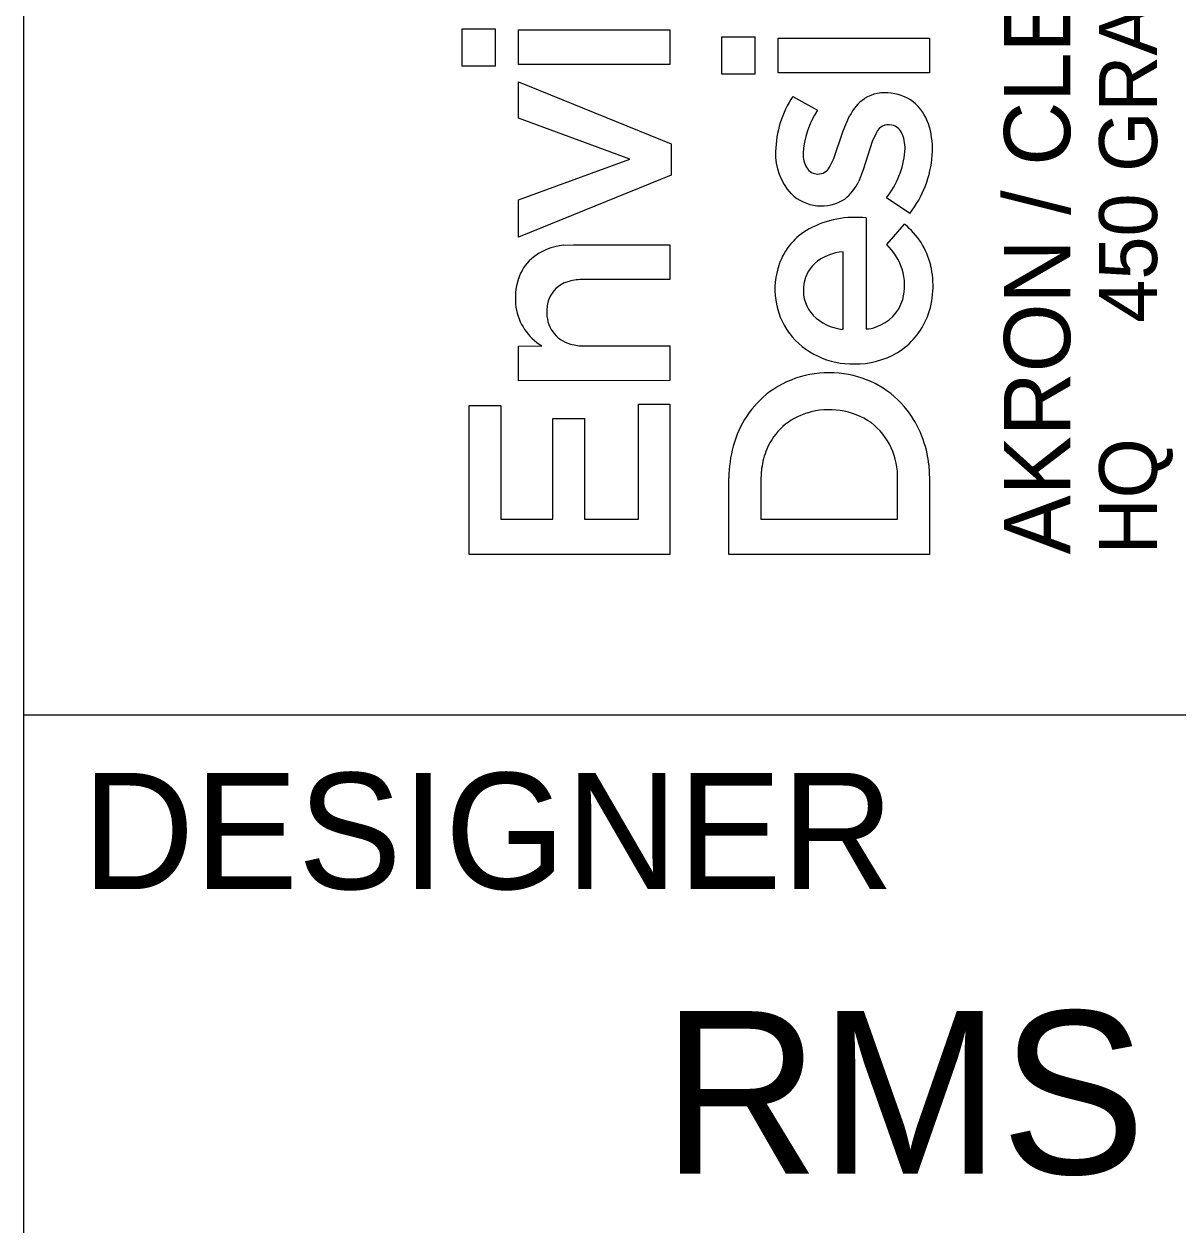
# Model space of a CAD drawing. Extents: x 2380994 to 2382560, y 256585 to 258122.
# Drawn here: x 2382520.03 to 2382539.89, y 257723.56 to 257744.23 of the extents above; entities that cross this region are included whole.
import ezdxf

# ---------------------------------------------------------------- set-up
doc = ezdxf.new("R2010")
doc.units = 0
doc.layers.add('RW_X_CL', color=7, linetype='Continuous')
doc.layers.add('SC_Scratch5', color=7, linetype='Continuous')

msp = doc.modelspace()

# ---------------------------------------------------------------- linework, layer by layer
at = {"layer": 'RW_X_CL'}
for p, q in [((2382527.573, 257743.506), (2382527.573, 257744.147)), ((2382527.573, 257744.147), (2382528.14, 257744.147)), ((2382528.14, 257744.147), (2382528.14, 257743.506)), ((2382528.54, 257743.53), (2382528.54, 257744.127)), ((2382528.54, 257744.127), (2382531.146, 257744.127)), ((2382531.146, 257744.127), (2382531.146, 257743.53)), ((2382532.042, 257743.364), (2382532.042, 257744.006)), ((2382532.042, 257744.006), (2382532.609, 257744.006)), ((2382532.609, 257744.006), (2382532.609, 257743.364)), ((2382533.009, 257743.389), (2382533.009, 257743.986)), ((2382533.009, 257743.986), (2382535.615, 257743.986)), ((2382535.615, 257743.986), (2382535.615, 257743.389)), ((2382528.14, 257743.506), (2382527.573, 257743.506)), ((2382531.146, 257743.53), (2382528.54, 257743.53)), ((2382532.609, 257743.364), (2382532.042, 257743.364)), ((2382535.615, 257743.389), (2382533.009, 257743.389)), ((2382528.54, 257742.607), (2382528.54, 257743.234)), ((2382528.54, 257743.234), (2382531.165, 257742.168)), ((2382533.262, 257742.983), (2382533.685, 257742.747)), ((2382530.455, 257741.901), (2382528.54, 257742.607)), ((2382534.128, 257742.393), (2382534.239, 257742.647)), ((2382533.966, 257741.915), (2382534.128, 257742.393)), ((2382534.7, 257742.362), (2382534.628, 257742.208)), ((2382531.165, 257742.168), (2382531.165, 257741.63)), ((2382534.628, 257742.208), (2382534.474, 257741.718)), ((2382528.54, 257741.201), (2382530.455, 257741.901)), ((2382533.891, 257741.765), (2382533.966, 257741.915)), ((2382534.474, 257741.718), (2382534.396, 257741.526)), ((2382531.165, 257741.63), (2382528.54, 257740.559)), ((2382528.54, 257740.559), (2382528.54, 257741.201)), ((2382535.274, 257740.97), (2382534.871, 257741.236)), ((2382534.522, 257740.891), (2382534.524, 257738.981)), ((2382534.877, 257740.435), (2382535.185, 257740.782)), ((2382529.319, 257740.421), (2382529.489, 257740.431)), ((2382529.489, 257740.431), (2382531.146, 257740.431)), ((2382531.146, 257740.431), (2382531.146, 257739.835)), ((2382534.129, 257738.978), (2382534.129, 257740.309)), ((2382531.146, 257739.835), (2382529.659, 257739.833)), ((2382534.104, 257738.975), (2382534.129, 257738.978)), ((2382528.54, 257738.687), (2382528.942, 257738.688)), ((2382528.54, 257738.091), (2382528.54, 257738.687)), ((2382529.676, 257738.688), (2382531.145, 257738.688)), ((2382531.145, 257738.688), (2382531.146, 257738.093)), ((2382531.146, 257738.093), (2382528.54, 257738.091)), ((2382527.691, 257735.1), (2382527.691, 257737.662)), ((2382527.691, 257737.662), (2382528.234, 257737.662)), ((2382528.234, 257737.662), (2382528.234, 257735.707)), ((2382530.603, 257735.707), (2382530.603, 257737.686)), ((2382530.603, 257737.686), (2382531.146, 257737.686)), ((2382531.146, 257737.686), (2382531.146, 257735.1)), ((2382529.132, 257735.707), (2382529.132, 257737.439)), ((2382529.132, 257737.439), (2382529.675, 257737.439)), ((2382529.675, 257737.439), (2382529.675, 257735.707)), ((2382532.724, 257736.578), (2382532.713, 257736.388)), ((2382535.601, 257736.641), (2382535.615, 257736.384)), ((2382532.16, 257735.102), (2382532.16, 257736.422)), ((2382532.713, 257736.388), (2382532.713, 257735.709)), ((2382535.061, 257735.709), (2382535.062, 257736.39)), ((2382535.615, 257736.384), (2382535.615, 257735.102)), ((2382528.234, 257735.707), (2382529.132, 257735.707)), ((2382529.675, 257735.707), (2382530.603, 257735.707)), ((2382532.713, 257735.709), (2382535.061, 257735.709)), ((2382531.146, 257735.1), (2382527.691, 257735.1)), ((2382535.615, 257735.102), (2382532.16, 257735.102))]:
    msp.add_line(p, q, dxfattribs=at)
for points in [[(2382527.573, 257743.506), (2382527.573, 257744.147), (2382528.14, 257744.147), (2382528.14, 257743.506)], [(2382528.54, 257743.53), (2382528.54, 257744.127), (2382531.146, 257744.127), (2382531.146, 257743.53)], [(2382532.042, 257743.364), (2382532.042, 257744.006), (2382532.609, 257744.006), (2382532.609, 257743.364)], [(2382533.009, 257743.389), (2382533.009, 257743.986), (2382535.615, 257743.986), (2382535.615, 257743.389)], [(2382528.54, 257740.559), (2382528.54, 257741.201), (2382530.455, 257741.901), (2382528.54, 257742.607), (2382528.54, 257743.234), (2382531.165, 257742.168), (2382531.165, 257741.63)], [(2382527.691, 257735.1), (2382527.691, 257737.662), (2382528.234, 257737.662), (2382528.234, 257735.707), (2382529.132, 257735.707), (2382529.132, 257737.439), (2382529.675, 257737.439), (2382529.675, 257735.707), (2382530.603, 257735.707), (2382530.603, 257737.686), (2382531.146, 257737.686), (2382531.146, 257735.1)]]:
    msp.add_lwpolyline(points, close=True, dxfattribs=at)
for points in [[(2382533.262, 257742.983), (2382533.685, 257742.747)], [(2382533.891, 257741.765), (2382533.966, 257741.915), (2382534.128, 257742.393), (2382534.239, 257742.647)], [(2382534.7, 257742.362), (2382534.628, 257742.208), (2382534.474, 257741.718), (2382534.396, 257741.526)], [(2382535.274, 257740.97), (2382534.871, 257741.236)], [(2382534.522, 257740.891), (2382534.524, 257738.981)], [(2382534.877, 257740.435), (2382535.185, 257740.782)], [(2382529.319, 257740.421), (2382529.489, 257740.431), (2382531.146, 257740.431), (2382531.146, 257739.835), (2382529.659, 257739.833)], [(2382534.104, 257738.975), (2382534.129, 257738.978), (2382534.129, 257740.309)], [(2382528.54, 257738.091), (2382528.54, 257738.687), (2382528.942, 257738.688)], [(2382529.676, 257738.688), (2382531.145, 257738.688), (2382531.146, 257738.093), (2382528.54, 257738.091)], [(2382535.601, 257736.641), (2382535.615, 257736.384), (2382535.615, 257735.102), (2382532.16, 257735.102)], [(2382532.724, 257736.578), (2382532.713, 257736.388), (2382532.713, 257735.709), (2382535.061, 257735.709), (2382535.062, 257736.39)], [(2382532.16, 257735.102), (2382532.16, 257736.422)]]:
    msp.add_lwpolyline(points, dxfattribs=at)
for centre, radius, start, end in [((2382534.759, 257741.994), 1.795, 146.531, 178.7571), ((2382534.759, 257741.994), 1.795, 146.531, 178.7571), ((2382534.964, 257742.284), 0.811, 125.5118, 153.4159), ((2382534.964, 257742.284), 0.811, 125.5118, 153.4159), ((2382534.844, 257742.394), 0.653, 80.1719, 122.5197), ((2382534.844, 257742.394), 0.653, 80.1719, 122.5197), ((2382534.887, 257742.307), 0.733, 47.7934, 84.6892), ((2382534.887, 257742.307), 0.733, 47.7934, 84.6892), ((2382534.935, 257741.92), 1.499, 146.5112, 176.9101), ((2382534.935, 257741.92), 1.499, 146.5112, 176.9101), ((2382534.789, 257742.234), 0.853, 14.9966, 46.2063), ((2382534.789, 257742.234), 0.853, 14.9966, 46.2063), ((2382534.908, 257742.268), 0.229, 76.6609, 155.7053), ((2382534.908, 257742.268), 0.229, 76.6609, 155.7053), ((2382534.911, 257742.244), 0.251, 21.5098, 78.5262), ((2382534.911, 257742.244), 0.251, 21.5098, 78.5262), ((2382534.55, 257742.095), 0.642, 354.5726, 22.068), ((2382534.55, 257742.095), 0.642, 354.5726, 22.068), ((2382534.24, 257742.077), 1.424, 355.8306, 15.3914), ((2382534.24, 257742.077), 1.424, 355.8306, 15.3914), ((2382533.965, 257741.989), 1.001, 177.5366, 222.7932), ((2382533.965, 257741.989), 1.001, 177.5366, 222.7932), ((2382533.893, 257741.989), 0.455, 178.4747, 211.0868), ((2382533.893, 257741.989), 0.455, 178.4747, 211.0868), ((2382533.681, 257742.172), 1.514, 321.811, 354.7969), ((2382533.681, 257742.172), 1.514, 321.811, 354.7969), ((2382533.822, 257742.106), 1.844, 321.9777, 355.8738), ((2382533.822, 257742.106), 1.844, 321.9777, 355.8738), ((2382533.698, 257741.876), 0.23, 212.2368, 268.3777), ((2382533.698, 257741.876), 0.23, 212.2368, 268.3777), ((2382533.7, 257741.86), 0.213, 267.716, 333.7337), ((2382533.7, 257741.86), 0.213, 267.716, 333.7337), ((2382533.651, 257741.858), 0.815, 308.0877, 335.9874), ((2382533.651, 257741.858), 0.815, 308.0877, 335.9874), ((2382533.751, 257741.849), 0.75, 225.9854, 302.4797), ((2382533.751, 257741.849), 0.75, 225.9854, 302.4797), ((2382534.336, 257739.225), 1.677, 83.615, 118.2876), ((2382534.336, 257739.225), 1.677, 83.615, 118.2876), ((2382534.079, 257739.723), 1.117, 118.8308, 160.6244), ((2382534.079, 257739.723), 1.117, 118.8308, 160.6244), ((2382534.38, 257739.775), 1.289, 13.5336, 51.3615), ((2382534.38, 257739.775), 1.289, 13.5336, 51.3615), ((2382529.406, 257739.427), 0.998, 94.9696, 130.2225), ((2382529.406, 257739.427), 0.998, 94.9696, 130.2225), ((2382534.188, 257739.464), 0.847, 94.008, 130.8817), ((2382534.188, 257739.464), 0.847, 94.008, 130.8817), ((2382534.107, 257739.653), 1.097, 19.0357, 45.4406), ((2382534.107, 257739.653), 1.097, 19.0357, 45.4406), ((2382529.301, 257739.594), 0.803, 132.2219, 161.6818), ((2382529.301, 257739.594), 0.803, 132.2219, 161.6818), ((2382534.24, 257739.664), 1.287, 160.5201, 215.7831), ((2382534.24, 257739.664), 1.287, 160.5201, 215.7831), ((2382534.041, 257739.667), 0.597, 132.9851, 177.179), ((2382534.041, 257739.667), 0.597, 132.9851, 177.179), ((2382534.158, 257739.726), 1.516, 339.3542, 13.3785), ((2382534.158, 257739.726), 1.516, 339.3542, 13.3785), ((2382529.606, 257739.506), 1.12, 162.2736, 187.7919), ((2382529.606, 257739.506), 1.12, 162.2736, 187.7919), ((2382529.653, 257738.913), 0.92, 89.6049, 105.3284), ((2382529.653, 257738.913), 0.92, 89.6049, 105.3284), ((2382534.245, 257739.736), 0.94, 344.6059, 17.007), ((2382534.245, 257739.736), 0.94, 344.6059, 17.007), ((2382529.528, 257739.315), 0.5, 103.6865, 182.2187), ((2382529.528, 257739.315), 0.5, 103.6865, 182.2187), ((2382534.065, 257739.643), 0.623, 175.0013, 223.283), ((2382534.065, 257739.643), 0.623, 175.0013, 223.283), ((2382534.479, 257739.685), 0.701, 288.0077, 343.5508), ((2382534.479, 257739.685), 0.701, 288.0077, 343.5508), ((2382529.437, 257739.502), 0.952, 188.962, 238.7037), ((2382529.437, 257739.502), 0.952, 188.962, 238.7037), ((2382529.578, 257739.253), 0.551, 175.5854, 255.1439), ((2382529.578, 257739.253), 0.551, 175.5854, 255.1439), ((2382534.21, 257739.814), 0.846, 225.0619, 262.7974), ((2382534.21, 257739.814), 0.846, 225.0619, 262.7974), ((2382534.526, 257739.385), 0.404, 269.7003, 294.8711), ((2382534.526, 257739.385), 0.404, 269.7003, 294.8711), ((2382534.41, 257739.646), 1.252, 300.9427, 338.7323), ((2382534.41, 257739.646), 1.252, 300.9427, 338.7323), ((2382534.282, 257739.753), 1.374, 217.7452, 271.6543), ((2382534.282, 257739.753), 1.374, 217.7452, 271.6543), ((2382529.668, 257739.531), 0.843, 254.0916, 270.5284), ((2382529.668, 257739.531), 0.843, 254.0916, 270.5284), ((2382534.341, 257739.79), 1.411, 269.2048, 300.3341), ((2382534.341, 257739.79), 1.411, 269.2048, 300.3341), ((2382533.877, 257736.5), 1.728, 81.194, 125.9984), ((2382533.877, 257736.5), 1.728, 81.194, 125.9984), ((2382533.923, 257736.568), 1.654, 37.8521, 82.402), ((2382533.923, 257736.568), 1.654, 37.8521, 82.402), ((2382533.909, 257736.52), 1.731, 127.2362, 165.148), ((2382533.909, 257736.52), 1.731, 127.2362, 165.148), ((2382533.887, 257736.314), 1.278, 55.6727, 107.2093), ((2382533.887, 257736.314), 1.278, 55.6727, 107.2093), ((2382533.749, 257736.455), 1.862, 5.7333, 37.304), ((2382533.749, 257736.455), 1.862, 5.7333, 37.304), ((2382533.81, 257736.498), 1.08, 106.1881, 157.3861), ((2382533.81, 257736.498), 1.08, 106.1881, 157.3861), ((2382533.89, 257736.442), 1.173, 357.4662, 52.2665), ((2382533.89, 257736.442), 1.173, 357.4662, 52.2665), ((2382534.317, 257736.398), 2.157, 164.7861, 179.3704), ((2382534.317, 257736.398), 2.157, 164.7861, 179.3704), ((2382533.997, 257736.42), 1.282, 157.3571, 172.9275), ((2382533.997, 257736.42), 1.282, 157.3571, 172.9275)]:
    msp.add_arc(centre, radius, start, end, dxfattribs=at)
at = {"layer": 'SC_Scratch5'}
for p, q in [((2382520.031, 257692.342), (2382520.031, 258112.342)), ((2382520.031, 257732.342), (2382550.031, 257732.342))]:
    msp.add_line(p, q, dxfattribs=at)

# ---------------------------------------------------------------- texts
at = {"layer": 'RW_X_CL'}
for s, height, p in [('450 GRANT ST., AKRON, OH  44311', 0.99692, (2382539.529, 257739.089)), ('AKRON / CLEVELAND / COLUMBUS', 1.13938, (2382538.034, 257735.102)), ('HQ ', 0.9969, (2382539.529, 257735.102))]:
    msp.add_text(s, height=height, rotation=90, dxfattribs=at).set_placement(p)
for s, height, p in [('DESIGNER', 2, (2382521.031, 257729.342)), ('RMS', 2.8, (2382531.014, 257724.442))]:
    msp.add_text(s, height=height, dxfattribs=at).set_placement(p)

doc.saveas('drawing.dxf')
